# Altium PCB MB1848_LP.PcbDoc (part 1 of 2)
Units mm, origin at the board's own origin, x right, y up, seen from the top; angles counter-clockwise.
Board outline 61.5 x 34 mm, 4 copper layers (Top Layer, MidLayer 1, MidLayer 2, Bottom Layer), stack 1.035 mm thick; 72 components, 64 nets, 238 pads, 1060 vias.
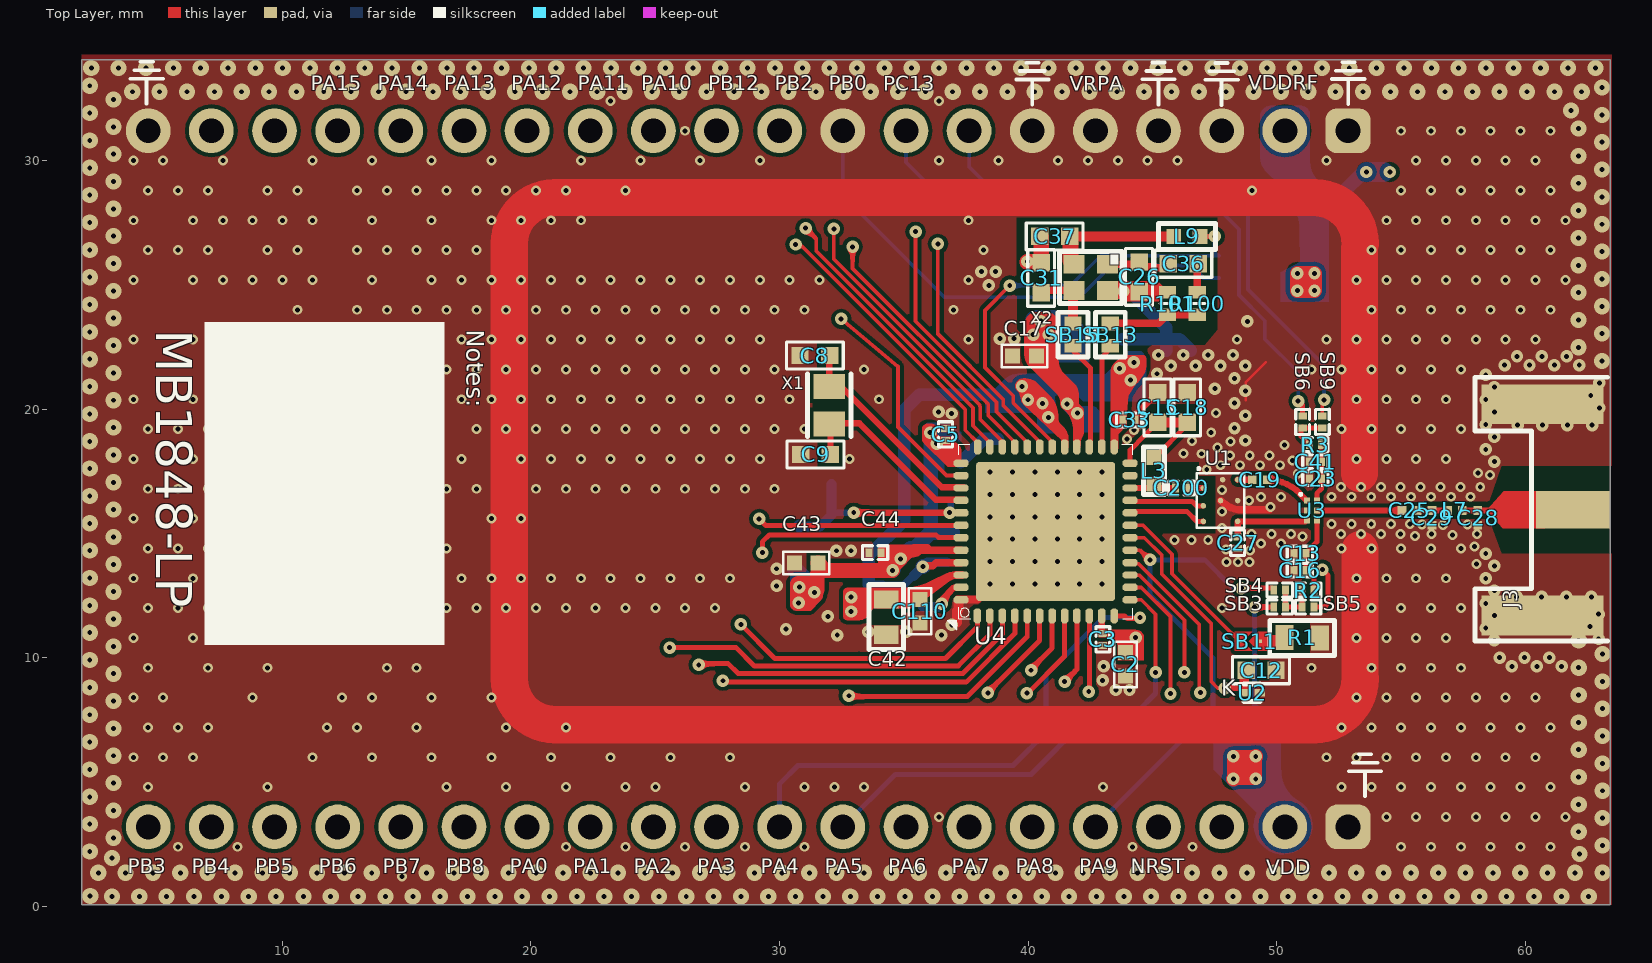
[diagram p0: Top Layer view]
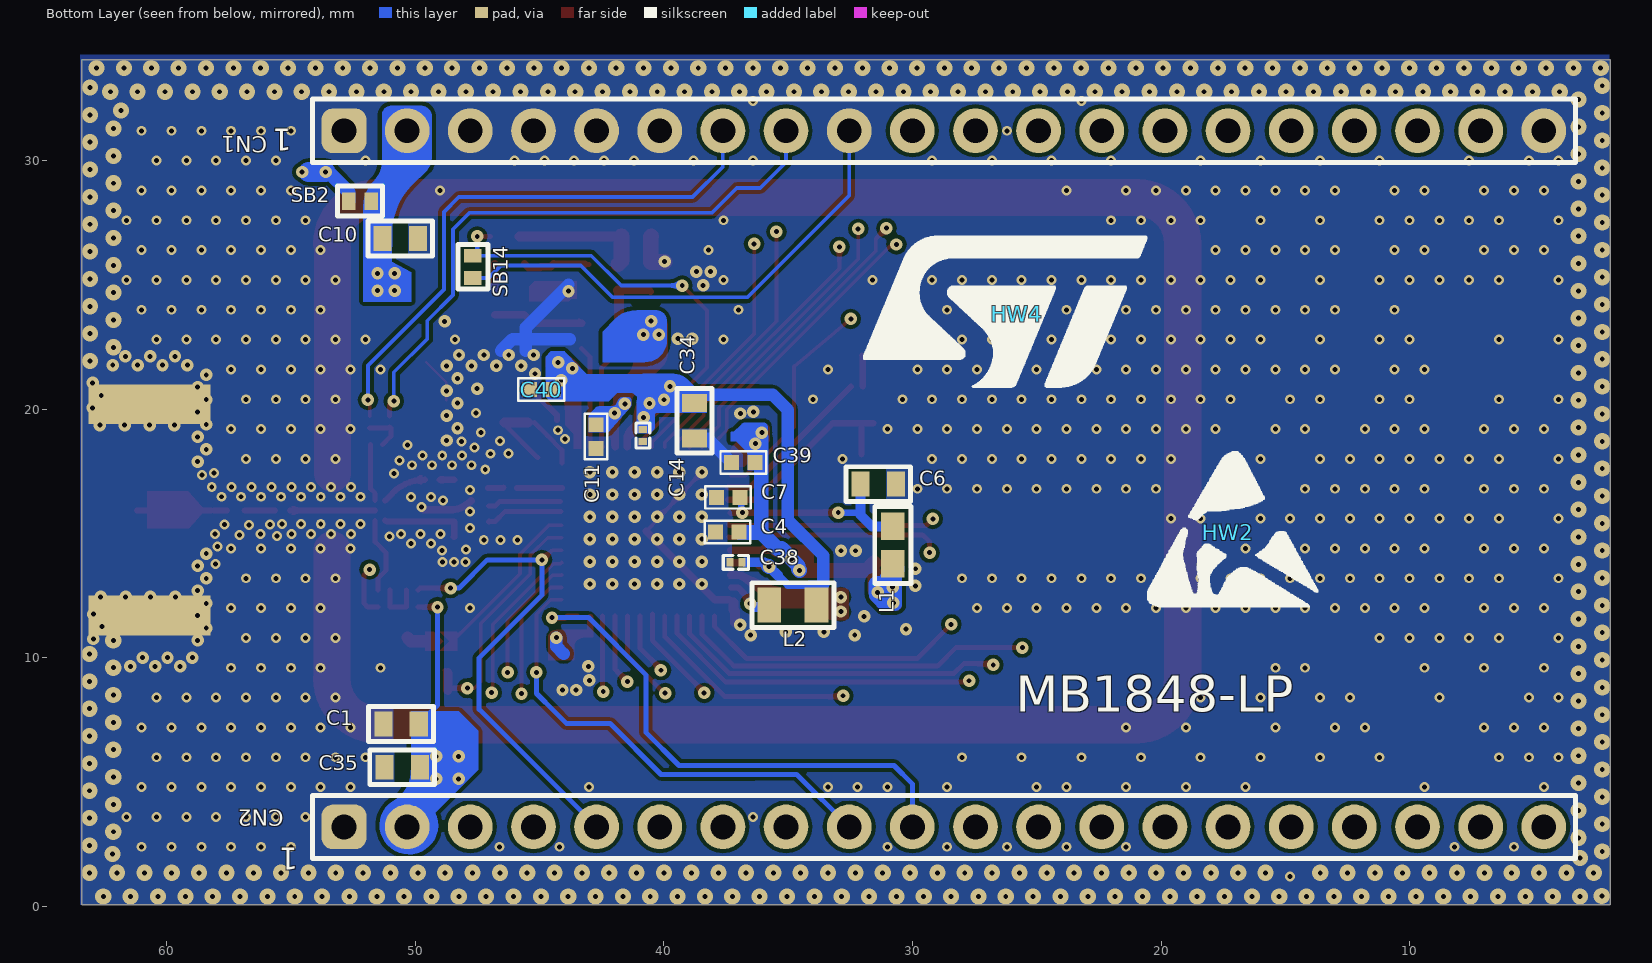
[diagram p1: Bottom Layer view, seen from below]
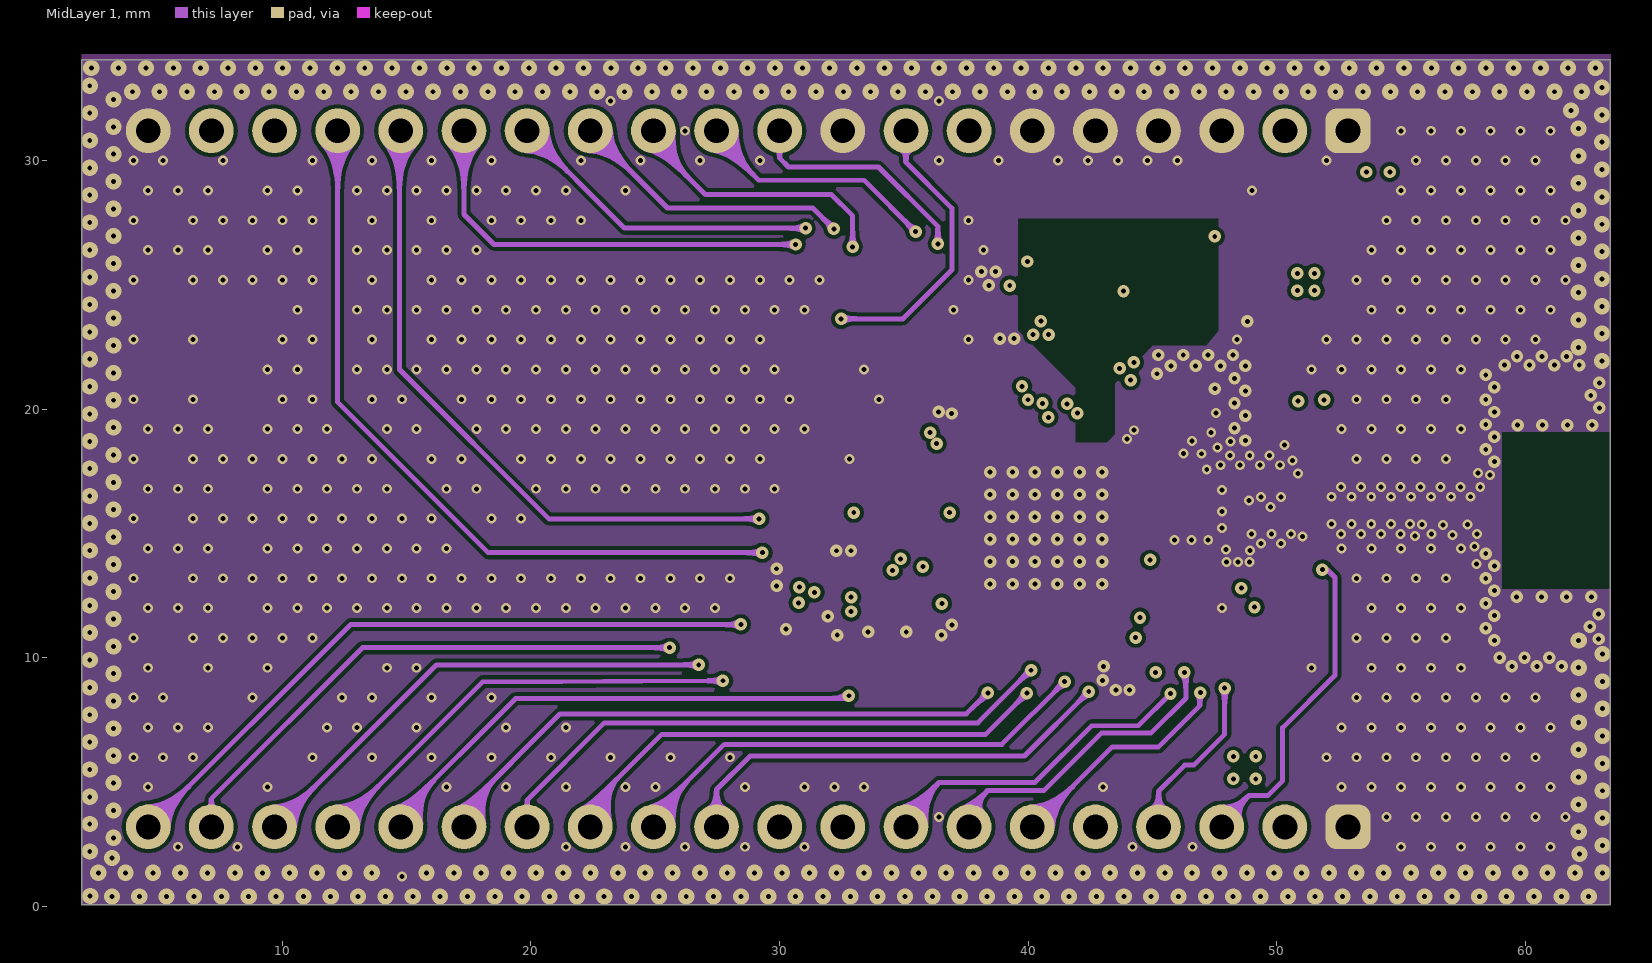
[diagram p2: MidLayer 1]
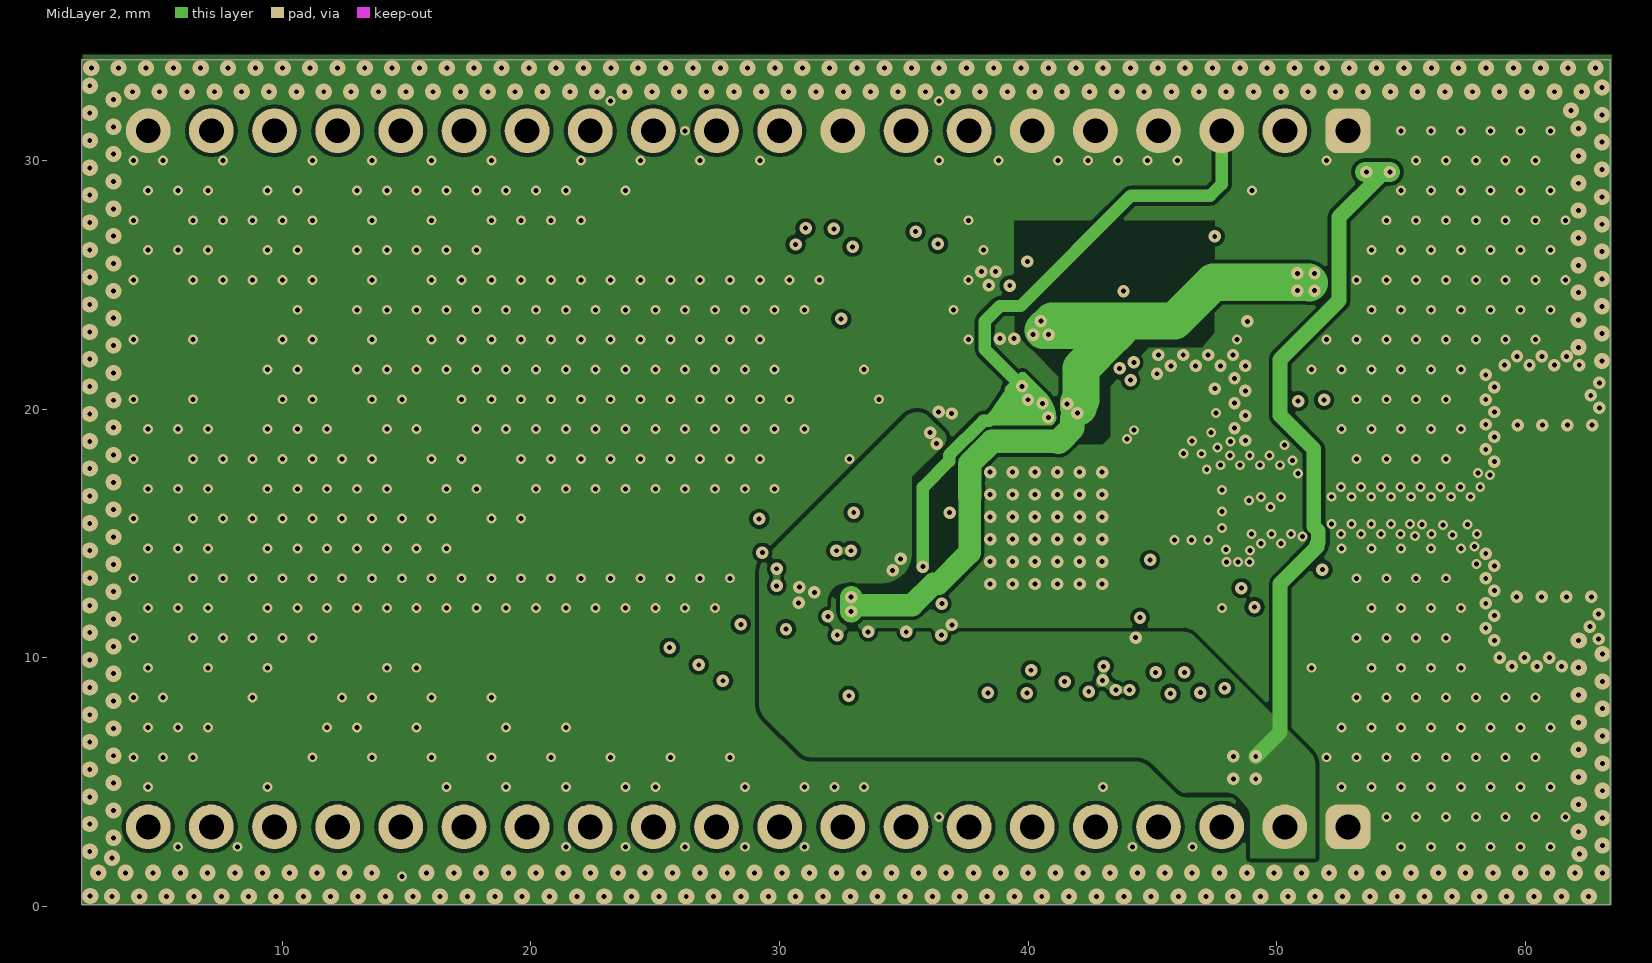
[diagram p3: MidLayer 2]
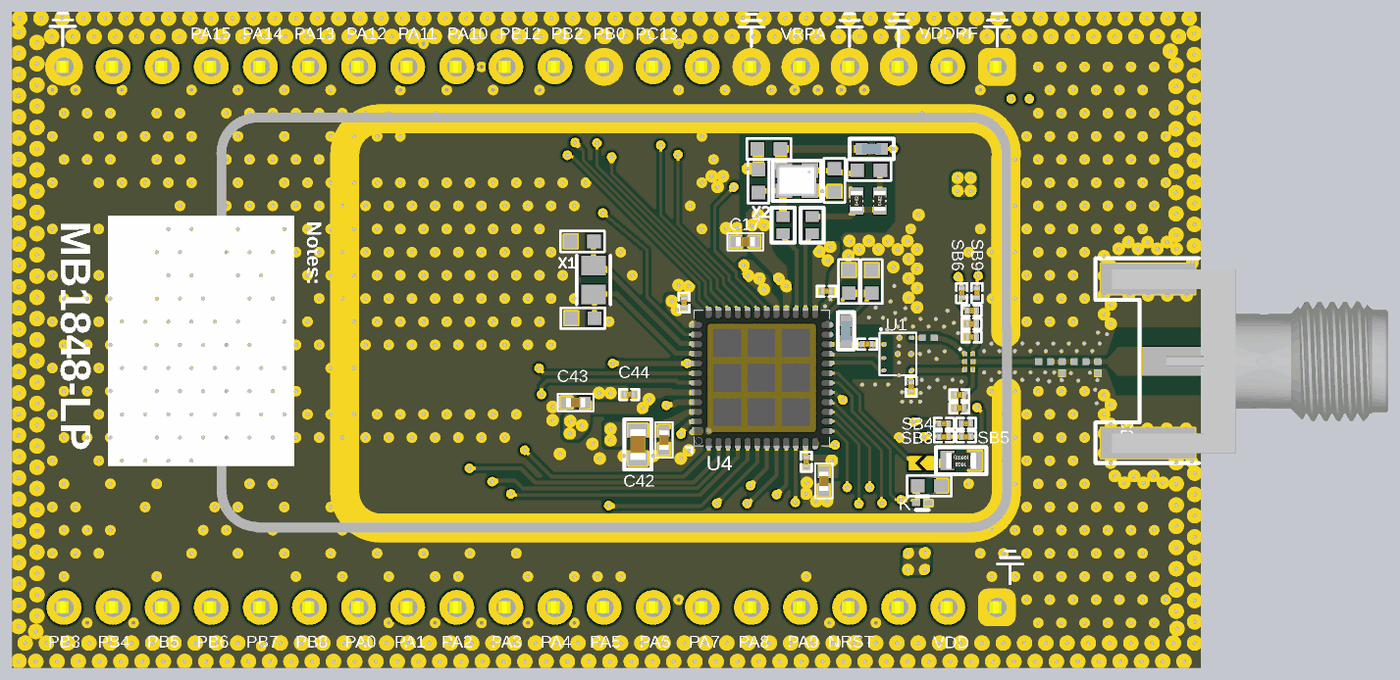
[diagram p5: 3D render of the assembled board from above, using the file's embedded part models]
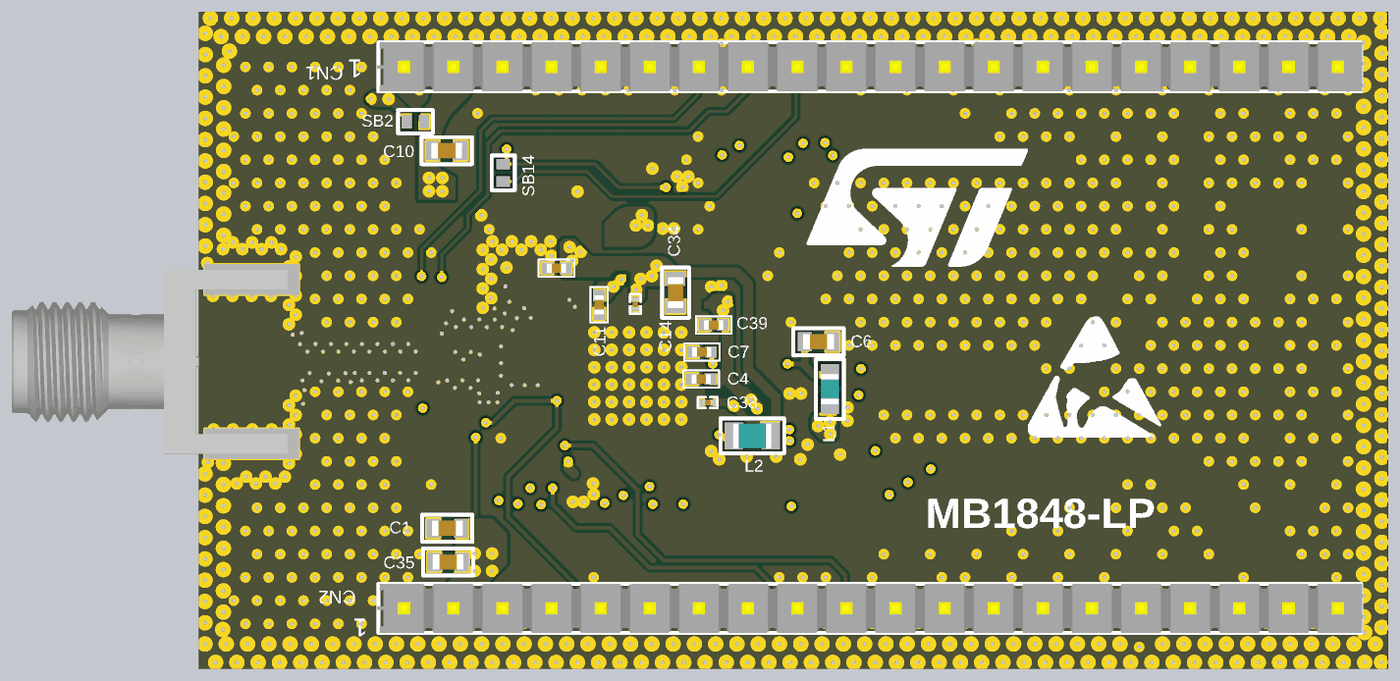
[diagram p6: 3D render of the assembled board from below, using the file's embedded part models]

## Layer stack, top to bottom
Top Solder: solder mask 0.01, Solder Resist, Dk 3.5
Top Layer: signal copper 0.035
Dielectric 2: prepreg 0.16, 1 x 2116 + 1 x 106, Dk 3.7
MidLayer 1: signal copper 0.0175
Dielectric 1: core 0.61, FR-4, Dk 5
MidLayer 2: signal copper 0.0175
Dielectric 3: prepreg 0.16, 1 x 2116 + 1 x 106, Dk 3.7
Bottom Layer: signal copper 0.035
Bottom Solder: solder mask 0.01, Solder Resist, Dk 3.5

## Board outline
1.922,0.056 63.42,0.056 63.42,34.056 1.942,34.056 1.922,34.056

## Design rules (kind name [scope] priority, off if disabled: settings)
BoardOutlineClearance [All] p1 off: gap=0.6 ignorepadtopadclearanceinfootprint=FALSE
Clearance Clearance_GND_50ohm [InNetClass('50ohm') or  (InDifferentialPairClass('All Differential Pairs')) vs InNamedPolygon('TOP_LAYER_GND')] p1: gap=0.175 ignorepadtopadclearanceinfootprint=FALSE except(0: Arc-Hole Track-Hole SMDPad-Hole THPad-Hole Via-Hole Fill-Hole Poly-Hole Region-Hole Text-Hole; 0.165: Arc-Fill Arc-Poly Arc-Region Track-Fill Track-Poly Track-Region)
Clearance Clearance_tab [(ObjectKind = 'Pad') And (Name Like 'Tab*-*') vs OnLayer('Keep-Out Layer')] p2: gap=0 ignorepadtopadclearanceinfootprint=FALSE
Clearance Clearance_via_to_via [(ObjectKind = 'Via') And (Net <> 'GND') vs (ObjectKind = 'Via') And (Net <> 'GND')] p3: gap=0.25 ignorepadtopadclearanceinfootprint=FALSE except(0: Arc-Hole Track-Hole SMDPad-Hole THPad-Hole Via-Hole Fill-Hole Poly-Hole Region-Hole Text-Hole)
Clearance [All] p4: gap=0.1 ignorepadtopadclearanceinfootprint=FALSE except(0: Arc-Hole Track-Hole SMDPad-Hole THPad-Hole Via-Hole Fill-Hole Poly-Hole Region-Hole Text-Hole; 0.15: Arc-Fill Arc-Poly Arc-Region Track-Fill Track-Poly Track-Region SMDPad-Fill SMDPad-Poly SMDPad-Region THPad-Fill THPad-Poly THPad-Region Via-Fill Via-Poly Via-Region Fill-Fill Fill-Poly Fill-Region Poly-Poly Poly-Region Region-Region)
ComponentClearance [All] p1: gap=0 collisioncheckmode=3 verticalgap=0.1 showdistances=FALSE
DiffPairsRouting [InDifferentialPair('RFI')] p1: maxlimit=0.3 minlimit=0.25 mostfreqgap=0.3 toplayer_minwidth=0.1 toplayer_maxwidth=0.24 toplayer_prefwidth=0.1 midlayer1_minwidth=0.145 midlayer1_maxwidth=0.24 midlayer1_prefwidth=0.145 midlayer2_minwidth=0.145 midlayer2_maxwidth=0.24 midlayer2_prefwidth=0.145 bottomlayer_minwidth=0.1 bottomlayer_maxwidth=0.24 bottomlayer_prefwidth=0.1 maxuncoupledlength=12.7
HoleSize [All] p1: absolutevalues=TRUE maxlimit=10 minlimit=0.025 maxpercent=80.000 minpercent=20.000
HoleToHoleClearance [All] p1: gap=0.25 allowstackedmicrovias=TRUE
MaximumViaCount MaximumViaCount_5 [InNet('GND')] p1: limit=1300
MaximumViaCount MaximumViaCount_4 [InNet('VDDRF1V55')] p2: limit=1000
MaximumViaCount MaximumViaCount_3 [InNet('VDDPA')] p3: limit=1000
MaximumViaCount MaximumViaCount_2 [InNet('VDDRF')] p4: limit=1000
MaximumViaCount MaximumViaCount_1 [InNet('VDD')] p5: limit=1000
MaximumViaCount [All] p6: limit=3
MinimumSolderMaskSliver [All] p1: minsoldermaskwidth=0.1
PlaneConnect [InNet('GND')] p1: planeconnectstyle=Relief reliefexpansion=0.508 reliefentries=4 reliefconductorwidth=0.21 reliefairgap=0.21
PolygonConnect PolygonConnect_J1 [(ObjectKind = 'Pad') And (Name = 'J1-2')] p1: connectstyle=Direct reliefconductorwidth=0.254 reliefentries=4 polygonreliefangle="90 Angle" airgapwidth=0.254
PolygonConnect PolygonConnect_All [All] p2: connectstyle=Direct reliefconductorwidth=0.25 reliefentries=4 polygonreliefangle="90 Angle" airgapwidth=0.25
RoutingLayers "RoutingLayers_90 Ohms" [InDifferentialPairClass('All Differential Pairs')] p1: top layer_v5=TRUE mid layer 1_v5=TRUE mid layer 2_v5=TRUE bottom layer_v5=TRUE
RoutingLayers [All] p2: top layer_v5=TRUE mid layer 1_v5=TRUE mid layer 2_v5=TRUE bottom layer_v5=TRUE
RoutingVias RoutingVias_BGA [InDrillLayerPair('Top Layer - MidLayer 1')] p1: holewidth=0.125 width=0.25 viastyle="Through Hole" minholewidth=0.125 minwidth=0.25 maxholewidth=0.125 maxwidth=0.3
RoutingVias [All] p2: holewidth=0.2 width=0.65 viastyle="Through Hole" minholewidth=0.2 minwidth=0.4 maxholewidth=0.2 maxwidth=0.7
ShortCircuit [(ObjectKind = 'Via') And (DrillPair = 'Top Layer - MidLayer 1') vs Ispad] p1: allowed=TRUE
SilkToSilkClearance [All] p1: silktosilkclearance=0.08
SilkToSolderMaskClearance [IsPad] p1: minsilkscreentomaskgap=0.08 clearancetoexposedcopper=TRUE
SolderMaskExpansion SolderMaskExpansion_VIA [IsVia] p1: expansion=-0.2 istentingtop=FALSE
SolderMaskExpansion [All] p2: expansion=0.075 istentingtop=FALSE
Width Width_50Ohms [InNetClass('50Ohms')] p1: maxlimit=0.7 minlimit=0.1 preferedwidth=0.24 midlayer1_maxwidth=0.5 midlayer2_maxwidth=0.5 bottomlayer_maxwidth=0.5 minimp=50.000000 maximp=50.000000 favimp=50.000000
Width [All] p2: maxlimit=2 minlimit=0.08 preferedwidth=0.15 toplayer_minwidth=0.097 toplayer_maxwidth=1.5 midlayer1_maxwidth=1 midlayer2_minwidth=0.1 bottomlayer_minwidth=0.1 bottomlayer_maxwidth=1.5 minimp=50.000000 maximp=50.000000 favimp=50.000000
20 further rules are at their usual default settings.

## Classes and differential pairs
net class 50ohm: NetC15_1 NetC19_1 NetC19_2 NetC25_1 NetC25_2 NetC27_2 NetC28_2
differential pair RFI: +RFI_P -RFI_N

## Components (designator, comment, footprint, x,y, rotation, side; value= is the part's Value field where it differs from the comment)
C1 "" CAPC1608X09N 50.569,7.332 r180 bottom
C2 "" CAPC1005X06N 43.909,9.73 r90 top
C3 "" 0201 43.003,10.492 r90 top
C4 "" CAPC1005X06N 37.443,15.048 r180 bottom
C5 "" 0201 36.673,19.222 r270 top
C6 "" CAPC1608X09N 31.375,16.977 r180 bottom
C7 "" CAPC1005X06N 37.41,16.448 r0 bottom
C8 "Capacitor" 0402 32.016,22.152 r180 top
C9 "Capacitor" 0402 32.043,18.172 r180 top
C10 "" CAPC1608X09N 50.599,26.863 r180 bottom
C11 "" CAPC1005X06N 42.723,18.892 r270 bottom
C12 "" 0402 48.768,9.492 r0 top
C13 "MCD-00198" 0201 50.687,14.2 r0 top
C14 "" CAPC1608X09N 38.769,19.522 r270 bottom
C15 "" 0402 45.203,19.467 r90 top
C16 "MCD-00102" 0201 50.687,13.515 r0 top
C17 "" CAPC1005X06N 39.851,22.134 r180 top
C18 "" 0402 46.393,20.663 r270 top
C19 "RFCapacitor_201" rlc_201_smd 49.311,17.158 r180 top
C23 "MCD-00198" 0201 51.312,17.196 r0 top
C25 "RFCapacitor_201" rlc_201_smd 55.336,15.919 r0 top
C26 "Capacitor" 0402 44.458,25.913 r270 top
C27 "NC" 0201 48.428,14.381 r90 top
C28 "RFCapacitor_201" rlc_201_smd 58.084,15.619 r90 top
C29 "RFCapacitor_201" rlc_201_smd 56.24,15.619 r90 top
C31 "Capacitor" 0402 40.521,24.68 r90 top
C33 "" 0201 44.296,19.562 r180 top
C34 "" 0201 40.843,18.693 r90 bottom
C35 "" CAPC1608X09N 50.527,5.593 r180 bottom
C36 "" 0402 46.836,25.842 r180 top
C37 "" 0402 40.468,26.942 r0 top
C38 "" 0201 36.863,13.832 r0 bottom
C39 "" CAPC1005X06N 36.802,17.848 r0 bottom
C40 "" CAPC1005X06N 44.93,20.782 r0 bottom
C41 "MCD-00102" 0201 51.792,17.882 r180 top
C42 "" CAPC1608X09N 34.292,11.632 r270 top
C43 "" CAPC1005X06N 31.071,13.802 r0 top
C44 "" 0201 33.6,14.223 r0 top
C110 "" CAPC1005X06N 35.642,11.864 r270 top
C200 "MCD-00198" 0201 46.398,16.826 r180 top
CN1 "CON20" CO_SAMTEC_TSW-120-07-X-S 28.733,31.192 r180 bottom
CN2 "CON20" CO_SAMTEC_TSW-120-07-X-S 28.733,3.192 r180 bottom
Designator16 "Comment" IMPEDANCE_TABLE 100.596,-33.043 r0 top
HW2 "Logo" LOGO_MAIN 17.315,15.048 r180 bottom
HW4 "Logo" LOGO_ST 25.803,23.812 r180 bottom
J3 "SMA" SMA_AMPHENOL_50ohms_Edge_PCB 63.432,15.945 r90 top
L1 "" INDC1608X95N 30.789,14.529 r90 bottom
L2 "" INDC2012X13N 34.803,12.112 r0 bottom
L3 "MCD-01330" IND_MURATA_LQW15A 45.057,17.52 r270 top
L7 "Ferrite" rlc_201_smd 57.162,15.919 r0 top
L9 "ferrite" IND_MURATA_LQW15A 46.383,26.942 r0 top
R1 "" RESC1608X05N 51.016,10.792 r180 top
R2 "MCD-00119" 0201 51.502,12.72 r180 top
R3 "MCD-00119" 0201 51.792,18.566 r180 top
R100 "Resistor" R0402 46.803,24.242 r90 top
R101 "Resistor" R0402 45.603,24.242 r90 top
SB2 "Open" SB_0402 52.218,28.363 r180 bottom
SB3 "Close" 0201 49.877,12.034 r0 top
SB4 "Open" 0201 49.877,12.718 r0 top
SB5 "Open" 0201 51.502,12.035 r180 top
SB6 "Close" 0201 51.041,19.72 r270 top
SB9 "Open" 0201 51.832,19.72 r270 top
SB11 "Close" GC_0402 48.953,10.661 r180 top
SB13 "Close" SB_0402 43.303,22.992 r90 top
SB14 "Open" SB_0402 47.678,25.719 r270 bottom
SB15 "Close" SB_0402 41.803,22.992 r90 top
U1 "IPD STM STM32WL" "IPD STM" 47.736,16.318 r180 top
U2 "" DIOM0603X03N 49.003,8.592 r0 top
U3 "BGS12SN6" TSNP-6-2 51.411,15.919 r0 top
U4 "STM32WLxx_QFN48" STM32WLXX_QFN48 40.701,15.075 r90 top
X1 "XTAL_2_PINS" OSC_NDK_NX2012SA 31.998,20.154 r90 top
X2 "" OSC_NDK_NX2016SA 42.513,25.295 r180 top

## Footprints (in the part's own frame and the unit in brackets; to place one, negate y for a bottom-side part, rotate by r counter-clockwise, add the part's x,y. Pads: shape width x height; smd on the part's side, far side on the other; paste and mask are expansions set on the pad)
0201 [mm]
  rect 0.28x0.35 smd: 1(0,0) 2(0.48,0)
  silkscreen extent -0.27,-0.28 0.75,0.28, body extent -0.06,-0.15 0.54,0.15, height 0.3
0402 [mm] "Chip Capacitor, Body 1.0x0.5mm, IPC High Density"
  rect 0.7x0.7 smd: 1(-0.001,0) 2(1.197,0)
  silkscreen extent -0.54,-0.54 1.74,0.54, body extent -0.42,-0.36 1.62,0.36, height 0.82
CAPC1005X06N [mm] "Chip Capacitor, 2-Leads, Body 1.00x0.70x0.70mm (0402)"
  rect 0.6x0.6 smd: 1(-0.475,0) 2(0.475,0)
  silkscreen extent -0.92,-0.45 0.92,0.45, body extent -0.5,-0.25 0.5,0.25, height 0.6
CAPC1608X09N [mm] "Chip Capacitor, 2-Leads, Body 1.60x0.80x0.90mm (0603)"
  rect 0.725x1 smd: 1(-0.713,0) 2(0.713,0)
  Top Layer pour cut-out: -0.3,0.7 0.3,0.7 0.3,-0.7 -0.3,-0.7
  silkscreen extent -1.3,-0.7 1.3,0.7, body extent -0.8,-0.4 0.8,0.4, height 0.9
CO_SAMTEC_TSW-120-07-X-S [mm] "Header, 20-Leads, 50.80x2.54x10.80mm, Pitch 2.54mm"
  rrect50% 1.8x1.8 hole 1: 1(-24.13,0)
  round 1.8 hole 1: 2(-21.59,0) 3(-19.05,0) 4(-16.51,0) 5(-13.97,0) 6(-11.43,0) 7(-8.89,0) 8(-6.35,0) 9(-3.81,0) 10(-1.27,0) 11(1.27,0) 12(3.81,0) 13(6.35,0) 14(8.89,0) 15(11.43,0) 16(13.97,0) 17(16.51,0) 18(19.05,0) 19(21.59,0) 20(24.13,0)
  silkscreen extent -25.4,-1.27 25.4,1.27, body extent -25.46,-1.27 25.46,1.27, height 8.38
DIOM0603X03N [mm] "Molded Diode, 2-Leads, Body 0.60x0.30mm"
  rect 0.425x0.3 smd: 1(-0.312,0) 2(0.313,0)
  silkscreen extent -0.32,-0.35 0.33,0.35, body extent -0.32,-0.18 0.33,0.18, height 0.33
GC_0402 [mm] "Grain de café format 0402"
  rect 0.15x0.15 smd paste-1: 1(-0.375,0) 2(0.45,0)
  Top Layer region: -0.65,0.375 -0.3,0.375 0.075,0 -0.3,-0.375 -0.65,-0.375
  Top Layer region: -0.05,0.375 0.65,0.375 0.65,-0.375 -0.05,-0.375 0.325,0
  body extent -0.5,-0.25 0.6,0.25, height 0.2
IMPEDANCE_TABLE [mm]
IND_MURATA_LQW15A [mm] "Inductor 2-Leads,Body 1.10x0.70x0.60mm(max)"
  rect 0.6x0.6 smd: 1(-0.53,0) 2(0.53,0)
  silkscreen extent -0.96,-0.42 0.96,0.42, body extent -0.5,-0.3 0.5,0.3, height 0.51
INDC1608X95N [mm] "Chip Inductor, 2-Leads, Body 1.75x0.95x0.95mm (0603)"
  rect 1.1x0.95 smd: 1(-0.75,0) 2(0.75,0)
  silkscreen extent -1.55,-0.72 1.55,0.72, body extent -0.8,-0.48 0.8,0.47, height 0.8
INDC2012X13N [mm] "Chip Inductor, 2-Leads, Body 2.0x1.2x1.3 (0805)"
  rect 0.96x1.4 smd: 1(-0.952,0) 2(0.952,0)
  silkscreen extent -1.65,-0.9 1.65,0.9, body extent -1,-0.65 1,0.65, height 1.18
"IPD STM" [mm] "IPD STM STM32WL, Body 2.20 x 1.90 x 0.710 mm (LxWxH max)"
  round 0.22 smd mask+0.05: 1(0.69,-0.5) 2(0.69,0.84) 3(0.69,0.21) 4(-0.69,0.84) 5(-0.69,0) 6(-0.69,-0.84) 7(-0.085,-0.84) 8(0,0)
  silkscreen extent -0.95,-1.33 0.95,1.1, body extent -0.84,-1 0.84,1, height 0.71
LOGO_MAIN [mm]
  silkscreen extent -3.24,-3.02 3.65,3.22
LOGO_ST [mm]
  silkscreen extent -6.18,-2.95 5.25,3.14
OSC_NDK_NX2012SA [mm] "Crystal, 2-Leads, Body 2.05x1.20x0.55mm (Tol:-/+0.05)"
  rect 1x1.25 smd: 1(-0.75,0) 2(0.75,0)
  silkscreen extent -1.25,-0.87 1.25,0.87, body extent -1.04,-0.63 1.03,0.63, height 0.55
OSC_NDK_NX2016SA [mm] "Crystal, 4-Leads, Body 2.10x1.61x0.50mm (max), Pitch 1.35x1.05mm"
  rect 0.85x0.75 smd: 1(-0.675,-0.525) 2(0.675,-0.525) 3(0.675,0.525) 4(-0.675,0.525)
  silkscreen extent -1.25,-1.05 1.25,1.05, body extent -1,-0.8 1,0.8, height 0.5
R0402 [mm]
  rect 0.51x0.7 smd mask+0.05: 1(-0.45,0) 2(0.45,0)
  silkscreen extent 0,-0.3 0,0.3, body extent -0.52,-0.3 0.52,0.3, height 0.4
RESC1608X05N [mm] "Chip Resistor, 2-Leads, Body 1.60x0.80mm (0603)"
  rect 0.725x1 smd: 1(-0.713,0) 2(0.712,-0.016)
  Top Layer pour cut-out: -0.3,0.7 0.3,0.7 0.3,-0.7 -0.3,-0.7
  silkscreen extent -1.3,-0.7 1.3,0.7, body extent -0.77,-0.42 0.78,0.43, height 0.45
rlc_201_smd [mm]
  rect 0.35x0.35 smd paste+0 mask+0.025: 1(-0.3,0) 2(0.3,0)
  body extent -0.3,-0.15 0.3,0.15, height 0.5
SB_0402 [mm] "Solder Bridge 0 Ohm (0402)"
  rect 0.55x0.7 smd: 1(-0.45,0) 2(0.45,0)
  silkscreen extent -0.9,-0.6 0.9,0.6, body extent -0.5,-0.25 0.5,0.25, height 0.25
SMA_AMPHENOL_50ohms_Edge_PCB [mm] "RF Connector, SMA End Launch Jack for 0.047 inch (1.19 mm thickness) PCB, 50 Ohm, Flat Tab Contact"
  rect 1.5x3 smd mask+0.05: 1(0,1.5)
  rect 1.6x4.9 smd mask+0.05: 2(-4.25,2.75) 2(4.25,2.75)
  rect 1.6x4.9 smd far side mask+0.05: 2(-4.25,2.75) 2(4.25,2.75)
  silkscreen extent -5.27,0.13 5.33,5.47, body extent -4.76,-9.65 4.76,4.62, height 4.09
STM32WLXX_QFN48 [mm] "QFN48 7x7x0.55mm pitch 0.5mm"
  oct 0.6x0.3 smd mask+0.06: 1(-3.398,2.746) 2(-3.398,2.239) 3(-3.398,1.739) 4(-3.398,1.239) 5(-3.398,0.739) 6(-3.398,0.239) 7(-3.398,-0.261) 8(-3.398,-0.761) 9(-3.398,-1.261) 10(-3.398,-1.761) 11(-3.398,-2.261) 12(-3.398,-2.761) 25(3.398,-2.761) 26(3.398,-2.261) 27(3.398,-1.761) 28(3.398,-1.261) 29(3.398,-0.761) 30(3.398,-0.261) 31(3.398,0.239) 32(3.398,0.739) 33(3.398,1.239) 34(3.398,1.739) 35(3.398,2.239) 36(3.398,2.739)
  oct 0.3x0.6 smd mask+0.06: 13(-2.752,-3.399) 14(-2.252,-3.399) 15(-1.752,-3.399) 16(-1.252,-3.399) 17(-0.752,-3.399) 18(-0.252,-3.399) 19(0.248,-3.399) 20(0.748,-3.399) 21(1.248,-3.399) 22(1.748,-3.399) 23(2.248,-3.399) 24(2.748,-3.399) 37(2.748,3.399) 38(2.248,3.399) 39(1.748,3.399) 40(1.248,3.399) 41(0.748,3.399) 42(0.248,3.399) 43(-0.252,3.399) 44(-0.752,3.399) 45(-1.252,3.399) 46(-1.752,3.399) 47(-2.252,3.399) 48(-2.752,3.399)
  rrect5% 5.6x5.6 smd paste-3 mask+0.08: 49(0,0)
  silkscreen extent -3.95,-3.5 3.5,3.96, body extent -3.51,-3.51 3.51,3.51, height 0.78
TSNP-6-2 [mm] "TSNP-6-2; Body 1.1 x 0.7 mm (LxW typ)"
  rect 0.25x0.25 smd paste-0.025 mask+0.025: 1(-0.2,0.4) 2(-0.2,0) 3(-0.2,-0.4) 4(0.2,-0.4) 5(0.2,0) 6(0.2,0.4)
  silkscreen extent -0.5,0.6 -0.4,0.7, body extent -0.35,-0.55 0.35,0.55, height 0.45

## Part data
C1 C6 C10 C35 C42: library part MCD-00009, "Capacitor, MLCC, 4.7uF, 16V, X5R, 10%, 0603, T=0.8mm"
C2 C4 C7 C11 C12 C17 C39 C40 C43 C110: library part MCD-00102, "Capacitor, MLCC, 100nF, 16V, X7R, 10%, 0402, T=0,5mm"
C3 C5 C44: library part MCD-00102, "Multilayer Ceramic Capacitors MLCC - SMD/SMT 0201 25VDC 0.1uF 10% X5R 0.3mm"
C8 C9 C26 C31: library part MCD-00003, "Capacitor, MLCC, 6.8pF, 50V, NPO, +-0.1pF, 0402, T=0.5mm"
C13 C23: "Multilayer ceramic capacitors X7R ±10%, 50V"
C14: library part MCD-00009, "Capacitor, MLCC, 4.7 uF, 16V, X5R, 10%, 0603, T=0.8mm"
C15: library part MCD-01123, "Capacitor, MLCC,47nF, 16V, X7R, 10%, 0402, T=0.5mm"
C16 C41: "Multilayer ceramic capacitors X5R ±10%, 10V"
C18: library part MCD-01123, "Capacitor, MLCC,68pF, 50V, C0G, 1%, 0402, T=0.5mm"
C19 C25: "Multilayer ceramic capacitors COG ±5%, 50V"
C27: library part RFCapacitor_201, "RF Capacitor High-Q, 0201"
C28 C29: "RF Capacitor High-Q, 0201"
C33 C34: library part MCD-00277, "Multilayer Ceramic Capacitors MLCC - SMD/SMT 0201 33pF 25volts C0G 5%"
C36 C37: library part MCD-00277, "Capacitor, MLCC, 33pF, 50V, NPO, 2%, 0402, T=0,5mm"
C38: library part MCD-01123, "Multilayer Ceramic Capacitors MLCC - SMD/SMT 0201 33pF 25volts C0G 5%"
C200: "Multilayer ceramic capacitors COG +/-5%, 50V"
CN1 CN2: "Connector right-angle, pitch 2.54mm, 20 contacts"
Designator16: library part MCD-00279
HW2: library part MCD-00627, "\"Hand\" ESD logo footprint for PCB"
HW4: library part MCD-00625, "\"STMicroelectronics\" logo footprint for PCB"
J3: "SMA Straight Connector"
L1: library part MCD-00047, "SMD Chip ferrite bead, 600R@100MHz +/-25%, 350mA, 500mohm DC, 0603, T=0.8mm"
L2: library part MCD-01433, "MLZ2012 Multilayer Shielded Inductor 15 uH, ±5%"
L3: "Inductor, 47nH, +-0.1nH, 140mA, 0402"
L7: library part RFInductor_201, "Thick Film Resistor ±5%, 1/20W"
L9: library part MCD-01330, "Inductor, 3.9nH, +-0.1nH, 750mA, 0402"
R1: library part MCD-00220, "Resistor,10K,0603,1%,1/10W"
R2 R3: "Thick Film Resistors - SMD 1/20watt 100ohms 5% 200ppm"
R100 R101: library part MCD-00052, "Resistor,0R,0402,5%,1/16W"
SB2 SB4 SB5 SB9 SB14: library part SB_Open, "Solder Bridge Open [0402] (Unpopulated)"
SB3 SB6: library part SB_0Ohm, "Thick Film Resistors - SMD 1/20watt ZEROohm Jumper"
SB11: library part Strap2, "Solder Jumper - Close"
SB13 SB15: library part SB_0Ohm, "Solder Bridge 0R [0402] (Populated with 0 Ohm)"
U1: library part "IPD ST STM32WL"
U2: library part MCD-00170, "ESD protection 6V1"
U3: "DC switch - Ultra-Low  SPDT analog switch"
U4: "STM32WL ARM MCU Multiprotocol LPWAN 32-bit Arm Cortex-M4 MCUs LoRa (G)FSK-MSK BPSK"
X1: library part MCD-01479, "Crystal 32.768kHz, 6pF, -+20PPM, R=80K, SMD"
X2: library part MCD-01446, "Crystal 32 MHz, 8pF, -+10 PPM, R=60O, SMD"

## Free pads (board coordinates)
  round 0.508 on Mech16: 1(22.892,-28.425) 1(71.739,-28.425)

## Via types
v1: diameter 0.4, hole 0.2, Top Layer to Bottom Layer, 477 vias
v2: diameter 0.65, hole 0.2, Top Layer to Bottom Layer, 317 vias
v3: diameter 0.5, hole 0.2, Top Layer to Bottom Layer, 189 vias
v4: diameter 0.4, hole 0.2, Top Layer to Bottom Layer, tented both sides, 77 vias

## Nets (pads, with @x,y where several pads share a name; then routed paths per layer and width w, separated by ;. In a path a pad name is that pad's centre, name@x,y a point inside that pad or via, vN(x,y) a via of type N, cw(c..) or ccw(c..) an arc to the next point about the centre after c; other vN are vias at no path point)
GND: C1.1 C2.1 C3.1 C4.1 C5.1 C6.2 C7.2 C8.2 C9.2 C10.2 C11.2 C12.2 C13.1 C14.2 C15.2 C16.1 C17.2 C18.1 C23.1 C26.2 C27.1 C28.1 C29.1 C31.2 C33.1 C34.1 C35.1 C37.1 C38.2 C39.2 C40.2 C41.2 C42.2 C43.1 C44.1 C110.2 CN1.1 CN1.3 CN1.4 CN1.5 CN1.6 CN1.9 CN1.20 CN2.1 J3.2 R1.1 R101.2 U1.5 U1.7 U1.8 U2.2 U3.2 U4.48 U4.49 X2.4 | length 128.4
  Top Layer w0.1: 48.758,20.355 48.758,21.084 49.564,21.889
  Top Layer w0.15: v3(38.471,17.462) 39.339,16.532 40.208,15.603 U4.49@40.701,15.075
  Top Layer w0.2: U4.48@37.302,12.324 U4.48@37.373,12.324
  Top Layer w0.25: C33.1@44.296,19.562 44.296,19.758 C15.2@45.203,20.664 ; 49.511,15.944 ccw(c49.572,16.004) 49.572,15.919 v4@49.711,15.919
  Top Layer w0.3: U4.48@37.373,12.324 37.949,12.324 U4.49@40.701,15.075 ; U1.8@47.736,16.318 ccw(c48.701,17.283) 48.464,15.939 cw(c48.524,15.519) 48.524,15.944 49.511,15.944
  Top Layer w0.4: v3@37.143,11.405 37.143,11.872 37.204,11.932 U4.48@37.204,12.224
  Top Layer w0.625: v3@39.964,25.913 40.521,25.913 40.521,26.924 C37.1@40.503,26.942 ; C26.2@44.368,24.77 C26.2@44.458,24.68
  Top Layer w1.5: 53.328,17.416 53.328,19.142 53.328,26.448 ; 53.35,9.106 53.35,10.742 53.35,11.942 53.35,14.335 ; 53.352,9.154 cw(c51.502,9.154) 51.502,7.304 43.525,7.304 21.403,7.304 20.977,7.304 cw(c20.977,9.154) 19.127,9.154 19.127,11.942 19.127,22.742 19.127,26.654 cw(c20.977,26.654) 20.977,28.504 23.803,28.504 49.003,28.504 51.502,28.504 cw(c51.502,26.654) 53.352,26.654
  Bottom Layer w0.5: C39.2@37.277,17.848 38.239,18.81 C14.2@38.769,18.81 ; 43.778,22.815 45.546,22.815 ; 43.833,24.991 45.546,23.279 45.546,22.815 ; 45.546,22.349 45.546,22.815 ; 46.546,22.349 46.081,22.815 45.546,22.815
  other v1: 14.803,1.192 5.803,2.392 8.203,2.392 21.403,2.392 23.803,2.392 26.203,2.392 28.603,2.392 31.003,2.392 44.203,2.392 46.603,2.392 55.003,2.392 56.203,2.392 57.403,2.392 58.603,2.392 59.803,2.392 61.003,2.392 36.403,3.592 54.403,3.592 55.603,3.592 56.803,3.592 58.003,3.592 59.203,3.592 60.403,3.592 61.603,3.592 4.603,4.792 9.403,4.792 16.603,4.792 19.003,4.792 21.403,4.792 23.803,4.792 25.003,4.792 28.603,4.792 31.003,4.792 32.203,4.792 33.403,4.792 43.003,4.792 52.603,4.792 53.803,4.792 55.003,4.792 56.203,4.792 57.403,4.792 58.603,4.792 59.803,4.792 61.003,4.792 4.003,5.992 5.203,5.992 6.403,5.992 11.203,5.992 13.603,5.992 16.003,5.992 18.403,5.992 20.803,5.992 23.203,5.992 25.603,5.992 28.003,5.992 52.003,5.992 53.203,5.992 54.403,5.992 55.603,5.992 56.803,5.992 58.003,5.992 59.203,5.992 60.403,5.992 4.603,7.192 5.803,7.192 7.003,7.192 11.803,7.192 13.003,7.192 15.403,7.192 19.003,7.192 21.403,7.192 52.603,7.192 53.803,7.192 55.003,7.192 56.203,7.192 57.403,7.192 58.603,7.192 59.803,7.192 61.003,7.192 4.003,8.392 5.203,8.392 8.803,8.392 12.403,8.392 13.603,8.392 16.003,8.392 18.403,8.392 53.203,8.392 54.403,8.392 55.603,8.392 56.803,8.392 58.003,8.392 59.203,8.392 60.403,8.392 4.603,9.592 7.003,9.592 9.403,9.592 14.203,9.592 15.403,9.592 51.403,9.592 53.803,9.592 55.003,9.592 56.203,9.592 57.403,9.592 4.003,10.792 6.403,10.792 7.603,10.792 8.803,10.792 10.003,10.792 11.203,10.792 53.203,10.792 54.403,10.792 55.603,10.792 56.803,10.792 4.603,11.992 5.803,11.992 7.003,11.992 9.403,11.992 10.603,11.992 11.803,11.992 13.003,11.992 14.203,11.992 15.403,11.992 16.603,11.992 17.803,11.992 19.003,11.992 20.203,11.992 21.403,11.992 22.603,11.992 23.803,11.992 25.003,11.992 26.203,11.992 27.403,11.992 47.803,11.992 53.803,11.992 55.003,11.992 56.203,11.992 57.403,11.992 4.003,13.192 6.403,13.192 7.603,13.192 8.803,13.192 10.003,13.192 11.203,13.192 12.403,13.192 13.603,13.192 14.803,13.192 16.003,13.192 17.203,13.192 18.403,13.192 19.603,13.192 20.803,13.192 22.003,13.192 23.203,13.192 24.403,13.192 25.603,13.192 26.803,13.192 28.003,13.192 53.203,13.192 54.403,13.192 55.603,13.192 56.803,13.192 4.603,14.392 5.803,14.392 7.003,14.392 9.403,14.392 10.603,14.392 11.803,14.392 13.003,14.392 14.203,14.392 15.403,14.392 16.603,14.392 52.603,14.392 53.803,14.392 55.003,14.392 56.203,14.392 57.403,14.392 4.003,15.592 6.403,15.592 7.603,15.592 8.803,15.592 10.003,15.592 11.203,15.592 12.403,15.592 13.603,15.592 14.803,15.592 16.003,15.592 18.403,15.592 19.603,15.592 4.603,16.792 5.803,16.792 7.003,16.792 9.403,16.792 10.603,16.792 11.803,16.792 13.003,16.792 14.203,16.792 16.603,16.792 17.803,16.792 20.203,16.792 21.403,16.792 22.603,16.792 23.803,16.792 25.003,16.792 26.203,16.792 27.403,16.792 28.603,16.792 29.803,16.792 4.003,17.992 6.403,17.992 7.603,17.992 8.803,17.992 10.003,17.992 11.203,17.992 12.403,17.992 13.603,17.992 16.003,17.992 17.203,17.992 19.603,17.992 20.803,17.992 22.003,17.992 23.203,17.992 24.403,17.992 25.603,17.992 26.803,17.992 28.003,17.992 29.203,17.992 32.803,17.992 53.203,17.992 54.403,17.992 55.603,17.992 56.803,17.992 4.603,19.192 5.803,19.192 7.003,19.192 9.403,19.192 10.603,19.192 11.803,19.192 14.203,19.192 15.403,19.192 17.803,19.192 19.003,19.192 20.203,19.192 21.403,19.192 22.603,19.192 23.803,19.192 25.003,19.192 26.203,19.192 27.403,19.192 28.603,19.192 29.803,19.192 31.003,19.192 52.603,19.192 53.803,19.192 55.003,19.192 56.203,19.192 57.403,19.192 4.003,20.392 6.403,20.392 10.003,20.392 11.203,20.392 13.603,20.392 14.803,20.392 17.203,20.392 18.403,20.392 19.603,20.392 20.803,20.392 22.003,20.392 23.203,20.392 24.403,20.392 25.603,20.392 26.803,20.392 28.003,20.392 29.203,20.392 30.403,20.392 34.003,20.392 53.203,20.392 54.403,20.392 55.603,20.392 56.803,20.392 9.403,21.592 10.603,21.592 13.003,21.592 14.203,21.592 15.403,21.592 16.603,21.592 17.803,21.592 19.003,21.592 20.203,21.592 21.403,21.592 22.603,21.592 23.803,21.592 25.003,21.592 26.203,21.592 27.403,21.592 28.603,21.592 29.803,21.592 33.403,21.592 51.403,21.592 52.603,21.592 53.803,21.592 55.003,21.592 56.203,21.592 57.403,21.592 4.003,22.792 6.403,22.792 10.003,22.792 11.203,22.792 13.603,22.792 16.003,22.792 17.203,22.792 18.403,22.792 19.603,22.792 20.803,22.792 22.003,22.792 23.203,22.792 24.403,22.792 25.603,22.792 26.803,22.792 28.003,22.792 29.203,22.792 37.603,22.792 48.403,22.792 52.003,22.792 53.203,22.792 54.403,22.792 55.603,22.792 56.803,22.792 58.003,22.792 59.203,22.792 60.403,22.792 10.603,23.992 13.003,23.992 14.203,23.992 15.403,23.992 16.603,23.992 17.803,23.992 19.003,23.992 20.203,23.992 21.403,23.992 22.603,23.992 23.803,23.992 25.003,23.992 26.203,23.992 27.403,23.992 28.603,23.992 29.803,23.992 31.003,23.992 37.003,23.992 53.803,23.992 55.003,23.992 56.203,23.992 57.403,23.992 58.603,23.992 59.803,23.992 61.003,23.992 4.003,25.192 6.403,25.192 7.603,25.192 8.803,25.192 10.003,25.192 11.203,25.192 13.603,25.192 16.003,25.192 17.203,25.192 18.403,25.192 19.603,25.192 20.803,25.192 22.003,25.192 23.203,25.192 24.403,25.192 25.603,25.192 26.803,25.192 28.003,25.192 29.203,25.192 30.403,25.192 31.603,25.192 37.603,25.192 53.203,25.192 54.403,25.192 55.603,25.192 56.803,25.192 58.003,25.192 59.203,25.192 60.403,25.192 61.603,25.192 4.603,26.392 5.803,26.392 7.003,26.392 9.403,26.392 10.603,26.392 13.003,26.392 14.203,26.392 15.403,26.392 16.603,26.392 17.803,26.392 38.203,26.392 53.803,26.392 55.003,26.392 56.203,26.392 57.403,26.392 58.603,26.392 59.803,26.392 61.003,26.392 4.003,27.592 6.403,27.592 7.603,27.592 8.803,27.592 10.003,27.592 11.203,27.592 13.603,27.592 16.003,27.592 18.403,27.592 19.603,27.592 20.803,27.592 22.003,27.592 37.603,27.592 54.403,27.592 55.603,27.592 56.803,27.592 58.003,27.592 59.203,27.592 60.403,27.592 61.603,27.592 4.603,28.792 5.803,28.792 7.003,28.792 9.403,28.792 10.603,28.792 13.003,28.792 14.203,28.792 15.403,28.792 16.603,28.792 17.803,28.792 19.003,28.792 20.203,28.792 21.403,28.792 23.803,28.792 49.003,28.792 55.003,28.792 56.203,28.792 57.403,28.792 58.603,28.792 59.803,28.792 61.003,28.792 4.003,29.992 5.203,29.992 7.603,29.992 11.203,29.992 13.603,29.992 16.003,29.992 18.403,29.992 22.003,29.992 24.403,29.992 26.803,29.992 29.203,29.992 36.403,29.992 38.803,29.992 41.203,29.992 42.403,29.992 43.603,29.992 44.803,29.992 46.003,29.992 52.003,29.992 55.603,29.992 56.803,29.992 58.003,29.992 59.203,29.992 60.403,29.992 26.203,31.192 55.003,31.192 56.203,31.192 57.403,31.192 58.603,31.192 59.803,31.192 61.003,31.192 23.203,32.392 36.403,32.392
  other v2: 2.269,0.408 3.145,0.393 4.245,0.393 5.345,0.393 6.445,0.393 7.545,0.393 8.645,0.393 9.745,0.393 10.845,0.393 11.945,0.393 13.045,0.393 14.145,0.393 15.245,0.393 16.345,0.393 17.445,0.393 18.545,0.393 19.645,0.393 20.745,0.393 21.845,0.393 22.945,0.393 24.045,0.393 25.145,0.393 26.245,0.393 27.345,0.393 28.445,0.393 29.545,0.393 30.645,0.393 31.745,0.393 32.845,0.393 33.945,0.393 35.045,0.393 36.145,0.393 37.245,0.393 38.345,0.393 39.445,0.393 40.545,0.393 41.645,0.393 42.745,0.393 43.845,0.393 44.945,0.393 46.045,0.393 47.145,0.393 48.245,0.393 49.345,0.393 50.445,0.393 51.545,0.393 52.645,0.393 53.745,0.393 54.845,0.393 55.945,0.393 57.045,0.393 58.145,0.393 59.245,0.393 60.345,0.393 61.445,0.393 62.545,0.393 2.595,1.345 3.695,1.345 4.795,1.345 5.895,1.345 6.995,1.345 8.095,1.345 9.195,1.345 10.295,1.345 11.395,1.345 12.495,1.345 13.595,1.345 15.795,1.345 16.895,1.345 17.995,1.345 19.095,1.345 20.195,1.345 21.295,1.345 22.395,1.345 23.495,1.345 24.595,1.345 25.695,1.345 26.795,1.345 27.895,1.345 28.995,1.345 30.095,1.345 31.195,1.345 32.295,1.345 33.395,1.345 34.495,1.345 35.595,1.345 36.695,1.345 37.795,1.345 38.895,1.345 39.995,1.345 41.095,1.345 42.195,1.345 43.295,1.345 44.395,1.345 45.495,1.345 46.595,1.345 47.695,1.345 48.795,1.345 49.895,1.345 50.995,1.345 52.095,1.345 53.195,1.345 54.295,1.345 55.395,1.345 56.495,1.345 57.595,1.345 58.695,1.345 59.795,1.345 60.895,1.345 61.995,1.345 63.095,1.345 3.146,1.945 62.179,2.096 2.252,2.202 63.095,2.445 3.205,2.752 62.142,2.995 2.252,3.302 63.095,3.545 3.205,3.852 62.142,4.095 2.252,4.402 63.095,4.645 3.205,4.952 62.142,5.195 2.252,5.502 63.095,5.745 3.205,6.052 62.142,6.295 2.252,6.602 63.095,6.845 3.205,7.152 62.142,7.395 2.252,7.702 63.095,7.945 3.205,8.252 62.142,8.495 2.252,8.802 63.095,9.045 3.205,9.352 62.142,9.595 2.252,9.902 63.095,10.145 3.205,10.452 62.142,10.695 2.252,11.002 3.205,11.552 2.252,12.102 3.205,12.652 2.252,13.202 3.205,13.752 2.252,14.302 3.205,14.852 2.252,15.402 3.205,15.952 2.252,16.502 3.205,17.052 2.252,17.602 3.205,18.152 2.252,18.702 3.205,19.252 2.252,19.802 3.205,20.352 2.252,20.902 3.205,21.452 63.081,21.931 2.252,22.002 62.128,22.481 3.205,22.552 63.081,23.031 2.252,23.102 62.128,23.581 3.205,23.652 63.081,24.131 2.252,24.202 62.128,24.681 3.205,24.752 63.081,25.231 2.252,25.302 62.128,25.781 3.205,25.852 63.081,26.331 2.252,26.402 62.128,26.881 3.205,26.952 63.081,27.431 2.252,27.502 62.128,27.981 3.205,28.052 63.081,28.531 2.252,28.602 62.128,29.081 3.205,29.152 63.081,29.631 2.252,29.702 62.128,30.181 3.205,30.252 63.081,30.731 2.252,30.802 62.128,31.281 3.205,31.352 63.081,31.831 2.252,31.902 61.832,32.009 3.205,32.452 3.964,32.761 5.064,32.761 6.164,32.761 7.264,32.761 8.364,32.761 9.464,32.761 10.564,32.761 11.664,32.761 12.764,32.761 13.864,32.761 14.964,32.761 16.064,32.761 17.164,32.761 18.264,32.761 19.364,32.761 20.464,32.761 21.564,32.761 22.664,32.761 23.764,32.761 24.864,32.761 25.964,32.761 27.064,32.761 28.164,32.761 29.264,32.761 30.364,32.761 31.464,32.761 32.564,32.761 33.664,32.761 34.764,32.761 35.864,32.761 36.964,32.761 38.064,32.761 39.164,32.761 40.264,32.761 41.364,32.761 42.464,32.761 43.564,32.761 44.664,32.761 45.764,32.761 46.864,32.761 47.964,32.761 49.064,32.761 50.164,32.761 51.264,32.761 52.364,32.761 53.464,32.761 54.564,32.761 55.664,32.761 56.764,32.761 57.864,32.761 58.964,32.761 60.064,32.761 61.164,32.761 62.264,32.761 63.081,32.931 2.252,33.002 2.314,33.714 3.414,33.714 4.514,33.714 5.614,33.714 6.714,33.714 7.814,33.714 8.914,33.714 10.014,33.714 11.114,33.714 12.214,33.714 13.314,33.714 14.414,33.714 15.514,33.714 16.614,33.714 17.714,33.714 18.814,33.714 19.914,33.714 21.014,33.714 22.114,33.714 23.214,33.714 24.314,33.714 25.414,33.714 26.514,33.714 27.614,33.714 28.714,33.714 29.814,33.714 30.914,33.714 32.014,33.714 33.114,33.714 34.214,33.714 35.314,33.714 36.414,33.714 37.514,33.714 38.614,33.714 39.714,33.714 40.814,33.714 41.914,33.714 43.014,33.714 44.114,33.714 45.214,33.714 46.314,33.714 47.414,33.714 48.514,33.714 49.614,33.714 50.714,33.714 51.814,33.714 52.914,33.714 54.014,33.714 55.114,33.714 56.214,33.714 57.314,33.714 58.414,33.714 59.514,33.714 60.614,33.714 61.714,33.714 62.814,33.714
  other v3: 43.525,8.698 44.075,8.698 42.995,9.087 43.035,9.646 59.458,9.648 60.458,9.648 61.458,9.648 58.962,9.997 59.962,9.997 60.962,9.997 58.754,10.691 62.943,10.749 32.319,10.902 36.51,10.903 33.564,11.038 35.094,11.038 30.258,11.148 58.404,11.186 62.594,11.244 36.927,11.32 31.94,11.658 58.754,11.691 62.943,11.749 58.404,12.186 59.649,12.442 60.649,12.442 61.649,12.442 62.649,12.442 58.754,12.691 29.882,12.889 38.471,12.962 39.371,12.962 40.271,12.962 41.171,12.962 42.071,12.962 42.971,12.962 58.404,13.186 29.882,13.575 58.754,13.691 38.471,13.862 39.371,13.862 40.271,13.862 41.171,13.862 42.071,13.862 42.971,13.862 58.404,14.186 32.283,14.299 32.873,14.299 38.471,14.762 39.371,14.762 40.271,14.762 41.171,14.762 42.071,14.762 42.971,14.762 38.471,15.662 39.371,15.662 40.271,15.662 41.171,15.662 42.071,15.662 42.971,15.662 38.471,16.562 39.371,16.562 40.271,16.562 41.171,16.562 42.071,16.562 42.971,16.562 39.371,17.462 40.271,17.462 41.171,17.462 42.071,17.462 42.971,17.462 58.754,17.881 58.404,18.376 48.736,18.734 58.754,18.881 48.297,19.234 59.683,19.354 60.683,19.354 61.683,19.354 62.683,19.354 58.404,19.376 48.736,19.734 36.924,19.821 36.398,19.884 58.754,19.881 62.978,20.048 48.297,20.234 58.404,20.376 62.628,20.552 48.736,20.734 47.509,20.817 58.754,20.881 62.978,21.048 48.297,21.234 58.404,21.376 45.181,21.418 45.736,21.734 46.736,21.734 47.736,21.734 48.736,21.734 59.165,21.768 60.165,21.768 61.165,21.768 62.165,21.768 59.66,22.117 60.66,22.117 61.66,22.117 45.236,22.173 46.236,22.173 47.236,22.173 48.236,22.173 38.856,22.834 39.435,22.834 48.815,23.523 43.833,24.741 38.415,24.973 38.114,25.524 38.693,25.524 39.964,25.932
  other v4: 58.027,13.773 47.971,13.847 48.435,13.847 48.897,13.847 48.921,14.306 47.959,14.346 57.949,14.471 49.365,14.589 50.165,14.589 45.891,14.733 46.566,14.733 47.241,14.733 51.035,14.881 55.565,14.901 57.072,14.937 48.981,14.978 49.781,14.978 50.571,14.98 52.582,14.977 53.382,14.977 54.182,14.977 54.982,14.977 56.215,14.972 58.059,14.972 47.8,15.218 56.688,15.326 52.199,15.366 52.999,15.366 53.799,15.366 54.599,15.366 55.364,15.367 55.832,15.361 57.675,15.361 47.8,15.878 49.743,16.063 48.887,16.321 49.36,16.452 50.16,16.452 52.199,16.471 52.999,16.471 53.799,16.471 54.599,16.471 55.399,16.471 56.199,16.471 56.999,16.471 57.799,16.471 47.8,16.736 52.582,16.86 53.382,16.86 54.182,16.86 54.982,16.86 55.782,16.86 56.582,16.86 57.382,16.86 58.182,16.86 58.566,17.347 50.853,17.401 58.093,17.43 47.182,17.572 47.728,17.739 48.528,17.739 49.328,17.739 50.128,17.739 50.64,17.929 48.111,18.128 48.911,18.128 49.711,18.128 46.25,18.21 46.972,18.2 47.605,18.444 50.311,18.557 48.13,18.698 46.591,18.717 43.973,18.787 47.362,19.048 44.258,19.147 47.562,19.841
NetC6_1: C6.1 C7.1 L1.2 U4.41 | length 8.4
  Top Layer w0.254: v3(32.983,15.832) v3(36.843,15.832) v3@36.883,15.832 ; v3@36.883,15.824 U4.41@37.302,15.824
  Bottom Layer w0.254: 32.087,15.742 32.177,15.832 v3(32.983,15.832) ; v3(36.843,15.832) 36.885,15.874 C7.1@36.885,16.212
  Bottom Layer w0.4: L1.2@30.789,15.279 31.625,15.279 32.087,15.742 C6.1@32.087,16.977
  Bottom Layer w0.5: L1.2@30.789,15.279 L1.2@30.842,15.331
NetC8_1: C8.1 U4.39 X1.2 | length 7.8
  Top Layer w0.254: X1.2@31.998,20.904 31.998,22.133 C8.1@32.017,22.152 ; X1.2@32.483,20.892 36.521,16.854 U4.39@37.404,16.854
NetC9_1: C9.1 U4.40 X1.1 | length 8.4
  Top Layer w0.254: X1.1@31.563,19.424 33.211,19.424 36.281,16.354 U4.40@37.404,16.354 ; X1.1@31.998,19.404 32.044,19.358 C9.1@32.044,18.172
NetC12_1: C12.1 CN2.4 U2.1 U4.18 | length 16.7
  Top Layer w0.15: U4.18@44.099,14.824 44.669,14.824 45.368,14.124 45.368,13.367 47.358,11.377 47.358,9.037 47.624,8.772 v3(47.903,8.772)
  Top Layer w0.2: v3(47.903,8.772) 48.611,8.772 U2.1@48.691,8.692 ; C12.1@48.691,9.379 C12.1@48.803,9.492
  Top Layer w0.4: U2.1@48.691,8.692 C12.1@48.691,9.379
  MidLayer 1 w0.2: CN2.4@45.243,3.192 45.243,4.622 46.294,5.673 46.661,5.673 47.903,6.915 v3(47.903,8.772)
NetC13_2: C13.2 C16.2 R2.1 U3.4 | length 3.1
  Top Layer w0.2: C13.2@51.167,14.2 C16.2@51.167,13.515 51.502,13.18 R2.1@51.502,12.72 ; C13.2@51.167,14.2 51.167,14.211 51.611,14.655 U3.4@51.611,15.519
NetC15_1: C15.1 C18.2 L3.1 U4.24 | length 4.9
  Top Layer w0.2: U4.24@44.099,17.824 44.099,18.348 44.692,18.941 ; 44.693,18.941 45.203,19.45 C15.1@45.203,19.466 ; L3.1@45.057,18.05 45.087,18.05 C18.2@46.401,19.364
  Top Layer w0.4: C15.1@45.468,19.453 C18.2@46.406,19.453
NetC19_1: C19.1 U3.1 | length 1.9
  Top Layer w0.25: C19.1@49.611,17.158 cw(c49.611,15.323) 50.909,16.621 U3.1@51.211,16.319
NetC19_2: C19.2 U1.6 | length 0.6
  Top Layer w0.25: U1.6@48.426,17.158 C19.2@49.011,17.158
NetC23_2: C23.2 C41.1 R3.1 U3.6 | length 2.3
  Top Layer w0.2: U3.6@51.611,16.319 51.611,16.605 51.792,16.786 C23.2@51.792,17.196 C41.1@51.792,17.882 R3.1@51.792,18.566
NetC25_1: C25.1 U3.5 | length 3.4
  Top Layer w0.25: U3.5@51.611,15.919 C25.1@55.036,15.919
NetC25_2: C25.2 C29.2 L7.1 | length 1.2
  Top Layer w0.25: C25.2@55.636,15.919 C29.2@56.24,15.919 L7.1@56.862,15.919
NetC26_1: C26.1 C36.2 X2.1 | length 2.7
  Top Layer w0.2: X2.1@42.998,25.82 X2.1@43.188,25.82 ; C26.1@44.4,25.82 C26.1@44.422,25.842
  Top Layer w0.3: X2.1@43.188,25.82 C26.1@44.4,25.82 ; C26.1@44.422,25.842 44.551,25.714 44.945,25.714 44.98,25.679 45.441,25.679 C36.2@45.603,25.842
NetC27_2: C27.2 U1.4 U3.3 | length 3.4
  Top Layer w0.25: C27.2@48.418,14.861 C27.2@48.428,14.861 C27.2@48.45,14.861 ; C27.2@48.426,14.898 U1.4@48.426,15.478 51.114,15.478 ccw(c51.114,15.616) U3.3@51.211,15.519
NetC28_2: C28.2 J3.1 L7.2 | length 3.5
  Top Layer w0.25: L7.2@57.584,15.919 C28.2@58.084,15.919 ; C28.2@58.206,15.919 J3.1@61.193,15.919
NetC31_1: C31.1 SB15.2 X2.3 | length 2.7
  Top Layer w0.254: C31.1@40.521,24.715 C31.1@40.576,24.77
  Top Layer w0.3: C31.1@40.576,24.77 X2.3@41.838,24.77
  Top Layer w0.4: SB15.2@41.803,23.442 41.803,24.735 X2.3@41.838,24.77
NetC36_1: C36.1 R100.2 | length 1.1
  Top Layer w0.3: R100.2@46.803,24.692 C36.1@46.803,25.84
NetC37_2: C37.2 L9.1 X2.2 | length 5.3
  Top Layer w0.4: C37.2@41.701,26.942 L9.1@45.803,26.942
  Top Layer w0.625: C37.2@41.701,26.942 41.701,25.957 X2.2@41.838,25.82
NetC200_1: C200.1 U1.1 | length 0.6
  Top Layer w0.25: C200.1@46.446,16.847 46.472,16.82 46.99,16.82 46.991,16.818 U1.1@47.046,16.818
NetC200_2: C200.2 L3.2 U4.22 | length 1.8
  Top Layer w0.25: U4.22@44.099,16.824 C200.2@45.892,16.824
NetCN1_7: CN1.7 SB9.1 | length 22.9
  Top Layer w0.15: SB9.1@51.832,19.72 51.832,20.291 v3@51.901,20.36
  Bottom Layer w0.15: CN1.7@37.623,31.192 37.623,29.742 38.841,28.524 48.246,28.524 48.844,27.926 48.844,24.809 51.901,21.751 v3(51.901,20.366)
NetCN1_8: CN1.8 SB6.1 U4.38 | length 44.8
  Top Layer w0.15: v3(32.477,23.623) 34.758,21.717 34.758,19.279 36.714,17.324 U4.38@37.302,17.324
  Top Layer w0.2: v3@50.871,20.337 51.041,20.167 SB6.1@51.041,19.72
  MidLayer 1 w0.2: v3(32.477,23.623) 34.957,23.623 36.928,25.594 36.928,28.076 35.083,29.921 CN1.8@35.083,31.192
  Bottom Layer w0.15: CN1.8@35.083,31.192 35.083,29.921 36.118,28.887 37.069,28.887 38.064,27.892 47.82,27.892 48.479,27.234 48.479,24.582 49.515,23.546 49.515,22.818 50.858,21.475 v3(50.858,20.319)
NetCN1_10: CN1.10 U4.31 | length 19.2
  Top Layer w0.15: v3(36.367,26.642) 36.367,23.015 38.998,20.383 38.998,20.139 40.461,18.676 U4.31@40.461,18.474
  MidLayer 1 w0.2: CN1.10@30.003,31.192 30.003,30.091 30.359,29.735 33.977,29.735 36.367,27.345 v3(36.367,26.642)
NetCN1_11: CN1.11 U4.32 | length 20.4
  Top Layer w0.15: v3@35.469,27.119 35.469,23.53 38.728,20.271 38.728,19.888 39.961,18.655 U4.32@39.961,18.474
  MidLayer 1 w0.2: CN1.11@27.463,31.192 27.463,30.896 29.158,29.201 33.399,29.201 v3(35.469,27.131)
NetCN1_12: CN1.12 U4.33 | length 21.7
  Top Layer w0.15: v3(32.937,26.523) 32.937,25.654 38.32,20.271 38.32,20.268 38.391,20.197 38.391,19.734 39.461,18.663 U4.33@39.461,18.474
  MidLayer 1 w0.2: CN1.12@24.923,31.192 24.923,30.718 27.014,28.628 32.081,28.628 32.937,27.772 v3(32.937,26.523)
NetCN1_13: CN1.13 U4.34 | length 23
  Top Layer w0.15: v3(32.18,27.243) 32.18,26.03 38.05,20.159 38.05,20.107 38.07,20.088 38.07,19.576 U4.34@38.961,18.684
  Top Layer w0.2: U4.34@38.961,18.474 U4.34@38.961,18.684
  MidLayer 1 w0.2: CN1.13@22.383,31.192 25.49,28.085 31.338,28.085 v3(32.18,27.243)
NetCN1_14: CN1.14 U4.35 | length 24.8
  Top Layer w0.15: v3@31.013,27.322 v3@31.093,27.322 ; v3(31.043,27.272) 31.473,26.842 31.473,26.354 37.78,20.047 37.78,19.324 38.461,18.643 U4.35@38.461,18.474
  MidLayer 1 w0.2: CN1.14@19.843,31.192 23.763,27.272 v3(31.043,27.272)
NetCN1_15: CN1.15 U4.36 | length 28.5
  Top Layer w0.15: v3(30.643,26.618) 30.724,26.536 30.907,26.536 37.468,19.975 37.468,19.147 37.961,18.654 U4.36@37.961,18.474
  MidLayer 1 w0.2: CN1.15@17.303,31.192 17.303,27.824 18.509,26.618 v3(30.643,26.618)
NetCN1_16: CN1.16 U4.42 | length 34.9
  Top Layer w0.2: v3(29.18,15.58) 29.449,15.312 37.361,15.312 U4.42@37.404,15.354
  MidLayer 1 w0.2: CN1.16@14.763,31.192 14.708,31.136 14.708,21.587 20.715,15.58 v3(29.18,15.58)
NetCN1_17: CN1.17 U4.43 | length 39.2
  Top Layer w0.2: v3(29.307,14.219) 29.307,14.654 29.595,14.942 36.286,14.942 36.39,14.838 37.372,14.838 U4.43@37.396,14.862
  MidLayer 1 w0.2: CN1.17@12.223,31.192 12.223,20.275 18.279,14.219 v3(29.307,14.219)
NetCN1_18: CN1.18
NetCN1_19: CN1.19
NetCN2_3: CN2.3 SB5.1 | length 15.1
  Top Layer w0.2: SB5.1@51.502,12.035 51.504,12.038 51.916,12.038 52.066,12.188 52.066,13.312 v3(51.835,13.543)
  MidLayer 1 w0.2: CN2.3@47.783,3.192 47.783,3.366 48.879,4.462 49.653,4.462 50.234,5.043 50.234,7.184 52.34,9.29 52.34,13.224 52.021,13.543 v3@51.844,13.543
NetCN2_5: CN2.5 SB4.1 U4.17 | length 20.2
  Top Layer w0.15: U4.17@44.099,14.324 44.492,14.324 44.883,13.932 v3@44.883,13.872
  Top Layer w0.2: v3@48.584,12.794 49.801,12.794 SB4.1@49.877,12.718
  Bottom Layer w0.2: CN2.5@42.703,3.192 47.429,7.918 47.429,9.988 44.903,12.515 v3(44.903,13.932) 47.098,13.932 48.235,12.794 v3(48.575,12.794)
